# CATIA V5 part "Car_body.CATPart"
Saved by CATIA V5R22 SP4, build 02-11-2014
Part number: Car_body
Bounding box of the stored display mesh (mm): x -1630 to 291.243, y -652.567 to 652.567, z -165.044 to 580
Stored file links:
  C:\DATA\Car_ASSY\教育モデル\5_ASM\Car_body.CATPart
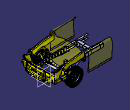
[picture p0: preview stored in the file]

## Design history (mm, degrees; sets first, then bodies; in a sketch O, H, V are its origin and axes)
Body1 (main body)
Body2 "Shass"
  Solid1: solid without history
  Translate1: ToTransfor Solid1, Direction (1, 0, 0), Length -5
Body3 "Body"
  Solid2: solid without history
